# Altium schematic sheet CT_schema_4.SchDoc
size 312 x 238 mm
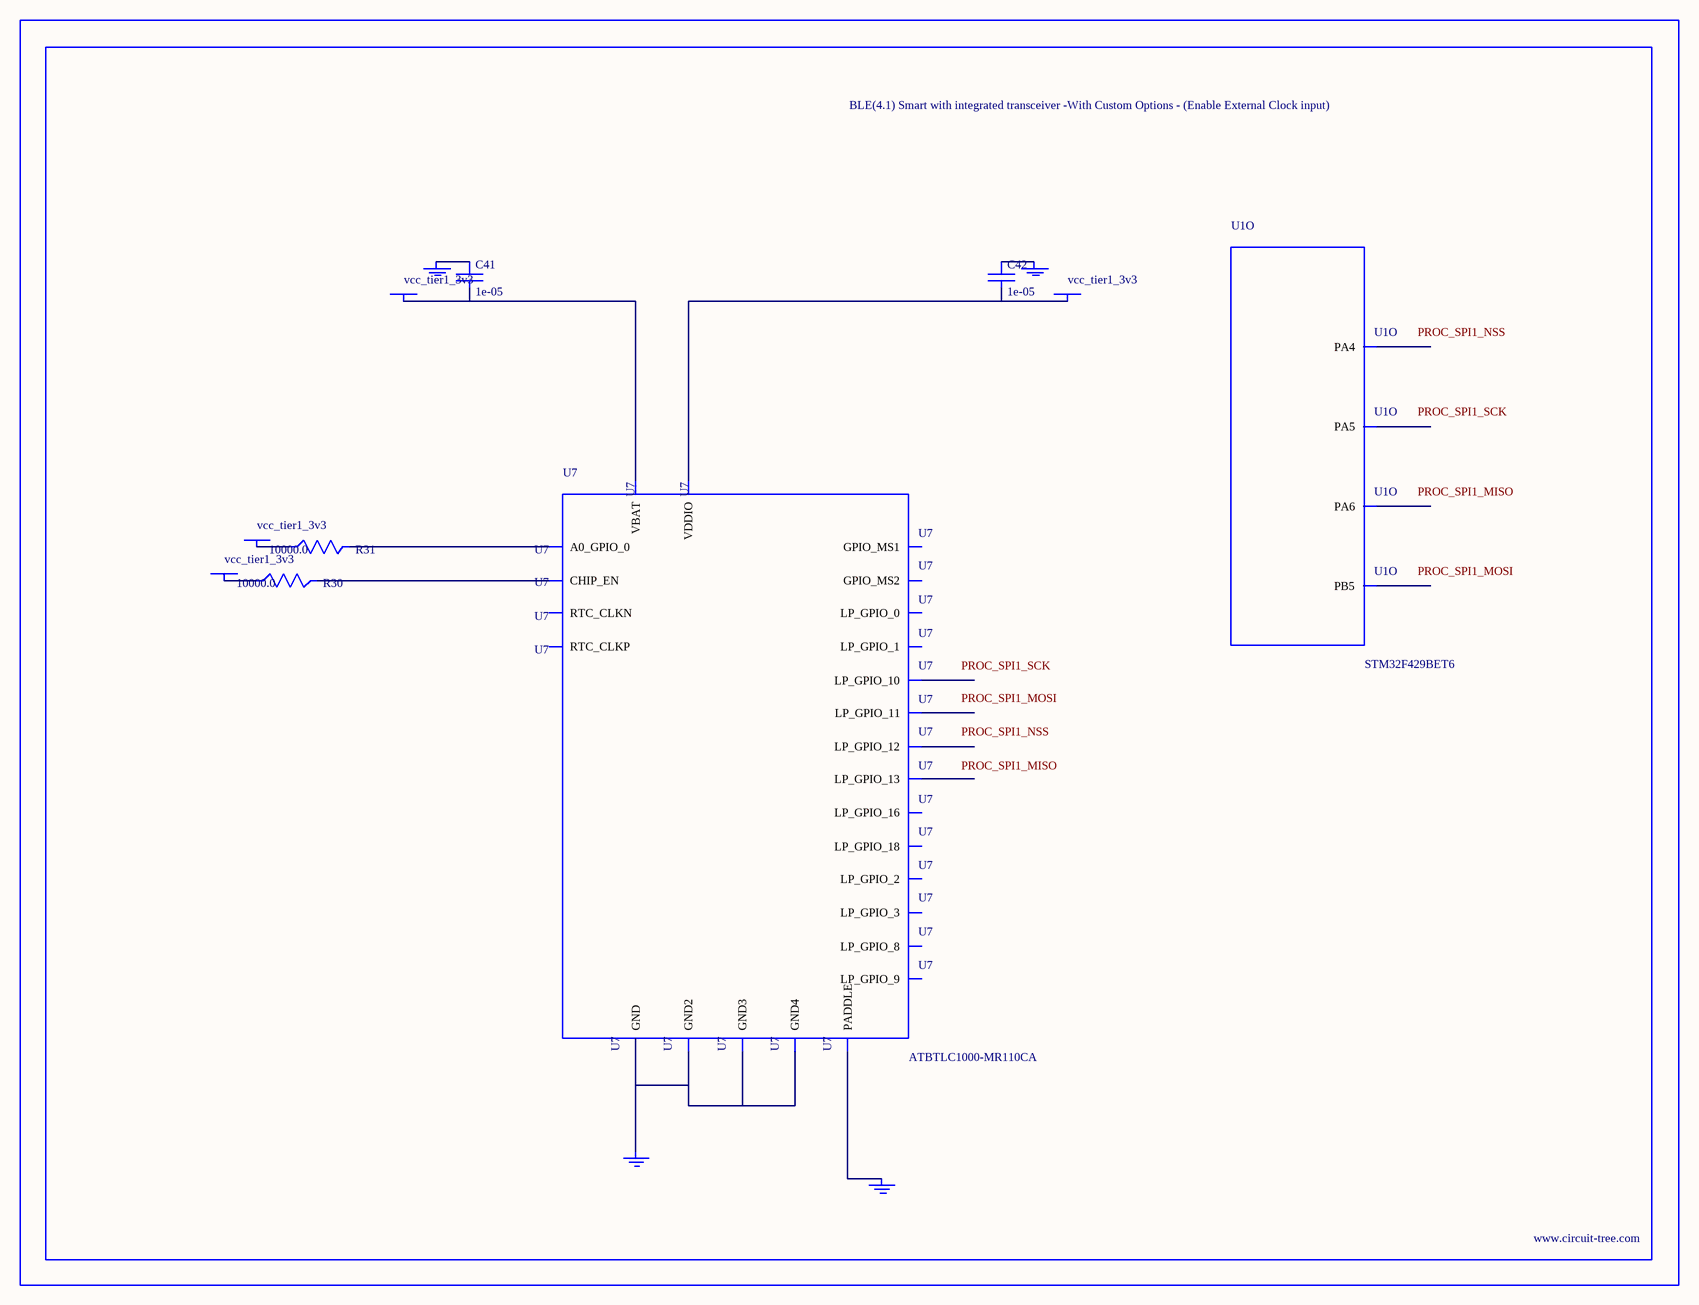
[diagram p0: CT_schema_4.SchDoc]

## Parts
BORDER3  (no value)
C41  1e-05  [C0805]
C42  1e-05  [C0805]
GND_INSTANCE_3_0  (no value)
GND_INSTANCE_3_1  (no value)
GND_INSTANCE_3_2  (no value)
GND_INSTANCE_3_3  (no value)
POWER_INSTANCE_3_0  vcc_tier1_3v3
POWER_INSTANCE_3_1  vcc_tier1_3v3
POWER_INSTANCE_3_2  vcc_tier1_3v3
POWER_INSTANCE_3_3  vcc_tier1_3v3
R30  10000.0  [R0603]
R31  10000.0  [R0603]
U1  STM32F429BET6  [LQFP208]  (part O of 16)
U7  ATBTLC1000-MR110CA  [ATBTLC1000-MR110CA]

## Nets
NetC41_1: C41.1 GND_INSTANCE_3_0.0(GND)
NetC41_2: C41.2 POWER_INSTANCE_3_0.0(PWR) U7.6(VBAT)
NetC42_1: C42.1 GND_INSTANCE_3_1.0(GND)
NetC42_2: C42.2 POWER_INSTANCE_3_3.0(PWR) U7.22(VDDIO)
NetGND_INSTANCE_3_2_0: GND_INSTANCE_3_2.0(GND) U7.25(PADDLE)
NetGND_INSTANCE_3_3_0: GND_INSTANCE_3_3.0(GND) U7.1(GND) U7.9(GND2) U7.13(GND3) U7.24(GND4)
NetPOWER_INSTANCE_3_1_0: POWER_INSTANCE_3_1.0(PWR) R30.1
NetPOWER_INSTANCE_3_2_0: POWER_INSTANCE_3_2.0(PWR) R31.1
NetR30_2: R30.2 U7.17(CHIP_EN)
NetR31_2: R31.2 U7.20(A0_GPIO_0)

Not connected (* = marked no-connect by the designer): U1 53(PA4) 54(PA5) 55(PA6) 194(PB5); U7 2(LP_GPIO_0) 3(LP_GPIO_1) 4(LP_GPIO_2) 5(LP_GPIO_3) 7(LP_GPIO_8) 8(LP_GPIO_9) 10(LP_GPIO_10) 11(LP_GPIO_11) 12(LP_GPIO_12) 14(LP_GPIO_13) 15(GPIO_MS1) 16(GPIO_MS2) 18(RTC_CLKP) 19(RTC_CLKN) 21(LP_GPIO_16) 23(LP_GPIO_18)

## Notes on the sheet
- Labels drawn without touching a wire or pin: PROC_SPI1_MISO, PROC_SPI1_MOSI, PROC_SPI1_NSS, PROC_SPI1_SCK

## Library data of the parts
BORDER3 = BORDER_PAGE3
C41 C42 = C0805C106K8RACTU
GND_INSTANCE_3_0-GND_INSTANCE_3_3 = GND
POWER_INSTANCE_3_0-POWER_INSTANCE_3_3 = PWR
R30 R31 = RC0603JR-0710KL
